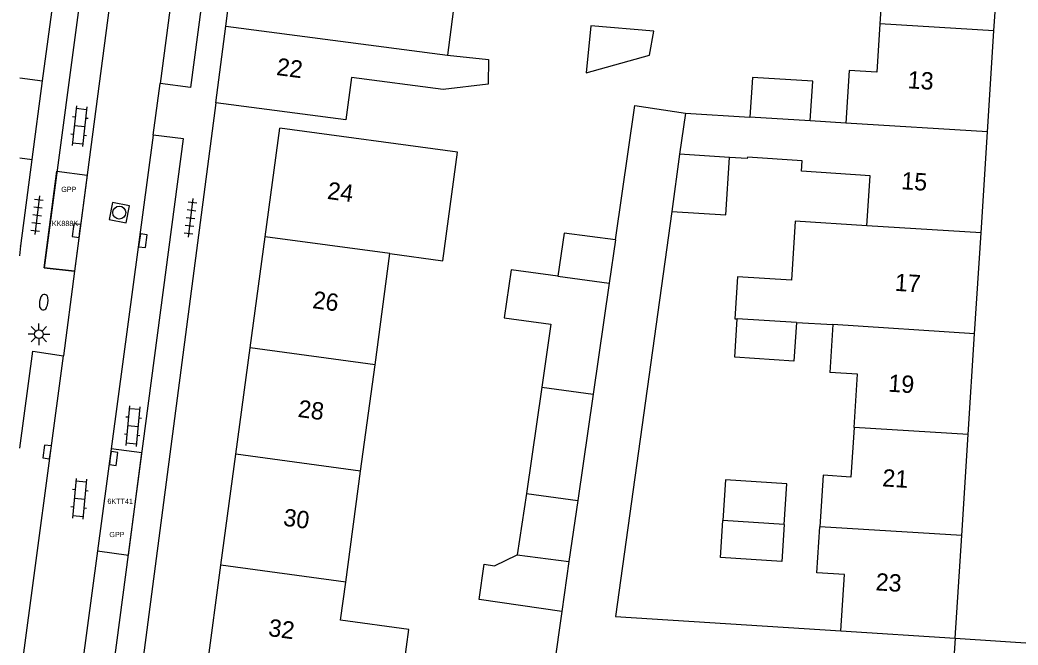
# Model space of a CAD drawing. Extents: x 132994 to 136000, y 393499 to 395512.
# Drawn here: x 133000 to 133057.6, y 395239.4 to 395275.5 of the extents above; entities that cross this region are included whole.
import ezdxf

# ---------------------------------------------------------------- set-up
doc = ezdxf.new("R2010")
doc.units = 0
for name, color, linetype in [('bp-anno-kenteken', 7, 'Continuous'), ('bp-grn-parkeervak', 7, 'Continuous'), ('gg-afsc-erfafscheiding', 7, 'Continuous'), ('gg-afsc-hekwerk', 7, 'Continuous'), ('gg-anno-huisnummerreeks BGT', 7, 'Continuous'), ('gg-bbg-gedigitaliseerde bebouwing', 7, 'Continuous'), ('gg-bbg-gedigitaliseerde bijgebouw', 7, 'Continuous'), ('gg-bbg-hoofdgebouw', 7, 'Continuous'), ('gg-bbg-luifel en loopbrug', 7, 'Continuous'), ('gg-bbg-tussenscheiding', 7, 'Continuous'), ('gg-knt-verharding', 7, 'Continuous'), ('gg-knt-verharding nz', 7, 'Continuous'), ('gt-symb-brandkraan', 7, 'Continuous'), ('gt-symb-klinker verharding', 7, 'Continuous'), ('gt-symb-kolk', 7, 'Continuous'), ('gt-symb-lichtmast', 7, 'Continuous'), ('gt-symb-rioolschacht', 7, 'Continuous'), ('gt-symb-tegel verharding', 7, 'Continuous'), ('kenmerkpunt gehandicapten parkeerplaats', 7, 'Continuous')]:
    doc.layers.add(name, color=color, linetype=linetype)

# ---------------------------------------------------------------- blocks, each defined once
blk = doc.blocks.new('gt0-KOLK')
at = {"layer": 'gt-symb-kolk'}
blk.add_lwpolyline([(0, 0), (0.375, 0), (0.375, 0.4), (-0.375, 0.4), (-0.375, 0), (0, 0)], dxfattribs=at)
blk = doc.blocks.new('gt0-TEG1')
at = {"layer": 'gt-symb-tegel verharding'}
for p, q in [((-1.125, 0), (1.125, 0)), ((-0.9, -0.25), (-0.9, 0.25)), ((-0.45, -0.25), (-0.45, 0.25)), ((0, -0.25), (0, 0.25)), ((0.45, -0.25), (0.45, 0.25)), ((0.9, -0.25), (0.9, 0.25))]:
    blk.add_line(p, q, dxfattribs=at)
blk = doc.blocks.new('gt0-RS')
at = {"layer": 'gt-symb-rioolschacht'}
blk.add_lwpolyline([(-0.5, -0.5), (0.5, -0.5), (0.5, 0.5), (-0.5, 0.5)], close=True, dxfattribs=at)
blk.add_circle((0, 0), 0.375, dxfattribs=at)
blk = doc.blocks.new('gt0-KL1')
at = {"layer": 'gt-symb-klinker verharding'}
for p, q in [((-1.15, 0.3), (1.15, 0.3)), ((-1, -0.3), (-1, 0.3)), ((-0.5, 0.3), (-0.5, 0.45)), ((0, -0.3), (0, 0.3)), ((0.5, 0.3), (0.5, 0.45)), ((1, -0.3), (1, 0.3)), ((-1.15, -0.3), (1.15, -0.3)), ((-0.5, -0.45), (-0.5, -0.3)), ((0.5, -0.45), (0.5, -0.3))]:
    blk.add_line(p, q, dxfattribs=at)
blk = doc.blocks.new('gt0-LMAST')
at = {"layer": 'gt-symb-lichtmast'}
for p, q in [((-0.005, 0.246), (-0.005, 0.621)), ((-0.182, 0.173), (-0.447, 0.438)), ((0.172, 0.173), (0.437, 0.438)), ((-0.255, -0.004), (-0.63, -0.004)), ((-0.182, -0.181), (-0.447, -0.446)), ((-0.005, -0.254), (-0.005, -0.629)), ((0.437, -0.446), (0.172, -0.181)), ((0.245, -0.004), (0.62, -0.004))]:
    blk.add_line(p, q, dxfattribs=at)
blk.add_circle((-0.005, -0.004), 0.25, dxfattribs=at)
blk = doc.blocks.new('gt0-BR')
at = {"layer": 'gt-symb-brandkraan'}
for centre, radius, start, end in [((-0.244, 0), 0.206, 107.56694, 252.43307), ((0.599, -2.664), 3, 106.89205, 107.56694), ((0, -0.691), 0.938, 73.10799, 106.89205), ((-0.599, -2.664), 3, 72.43309, 73.10799), ((0.244, 0), 0.206, 287.56695, 72.43309), ((0.599, 2.664), 3, 252.43307, 253.10797), ((0, 0.691), 0.938, 253.10797, 286.89206), ((-0.599, 2.664), 3, 286.89206, 287.56695)]:
    blk.add_arc(centre, radius, start, end, dxfattribs=at)

msp = doc.modelspace()

# ---------------------------------------------------------------- linework, layer by layer
at = {"layer": 'bp-grn-parkeervak'}
for points in [[(133003.147, 395261.009), (133001.393, 395261.218), (133002.134, 395266.793), (133003.879, 395266.563), (133003.147, 395261.009)], [(133004.476, 395244.873), (133006.259, 395244.635), (133007.04, 395250.53), (133005.262, 395250.767), (133004.476, 395244.873)]]:
    msp.add_lwpolyline(points, dxfattribs=at)
at = {"layer": 'gg-afsc-erfafscheiding'}
for p, q in [((133031.274, 395241.382), (133030.751, 395237.839)), ((133053.96, 395239.83), (133058.979, 395239.513))]:
    msp.add_line(p, q, dxfattribs=at)
for points in [[(133034.364, 395262.817), (133035.481, 395270.573), (133038.409, 395270.137)], [(133037.608, 395264.469), (133034.37, 395241.085), (133047.367, 395240.253)]]:
    msp.add_lwpolyline(points, dxfattribs=at)
at = {"layer": 'gg-afsc-hekwerk'}
msp.add_line((133053.96, 395239.83), (133053.832, 395237.8), dxfattribs=at)
at = {"layer": 'gg-bbg-gedigitaliseerde bebouwing'}
for p, q in [((133038.409, 395270.137), (133038.064, 395267.759)), ((133038.409, 395270.137), (133042.121, 395269.899)), ((133047.653, 395269.564), (133045.603, 395269.695)), ((133040.937, 395267.576), (133038.064, 395267.759)), ((133000, 395262.491), (133000.045, 395262.485)), ((133020.486, 395255.619), (133021.35, 395262.031)), ((133044.797, 395258.05), (133046.908, 395257.931)), ((133046.908, 395257.931), (133046.731, 395255.173)), ((133019.658, 395249.475), (133020.486, 395255.619)), ((133018.795, 395243.07), (133019.658, 395249.475)), ((133047.367, 395240.253), (133053.96, 395239.83))]:
    msp.add_line(p, q, dxfattribs=at)
for points in [[(133056.57, 395280.69), (133048.398, 395281.214), (133048.214, 395278.337), (133049.808, 395278.235), (133049.619, 395275.289)], [(133020.021, 395278.41), (133019.794, 395276.674), (133025.002, 395275.992), (133024.672, 395273.473)], [(133049.619, 395275.289), (133049.439, 395272.492), (133047.847, 395272.594), (133047.653, 395269.564)], [(133024.672, 395273.473), (133027.029, 395273.227), (133027.012, 395271.801), (133024.415, 395271.509), (133019.13, 395272.201), (133018.808, 395269.746), (133011.3, 395270.73)], [(133021.35, 395262.031), (133024.399, 395261.62), (133025.243, 395267.886), (133014.99, 395269.27)], [(133048.87, 395263.641), (133049.055, 395266.525), (133045.091, 395266.779), (133045.13, 395267.391), (133041.974, 395267.594), (133041.968, 395267.51), (133040.937, 395267.576)], [(133048.87, 395263.641), (133044.72, 395263.897), (133044.509, 395260.5), (133041.406, 395260.693), (133041.256, 395258.264), (133041.387, 395258.256)], [(133048.124, 395251.992), (133048.321, 395255.071), (133046.731, 395255.173)], [(133048.124, 395251.992), (133047.941, 395249.132), (133046.351, 395249.234), (133046.161, 395246.267)], [(133047.367, 395240.253), (133047.577, 395243.505), (133045.988, 395243.607), (133046.161, 395246.267)], [(133017.96, 395236.875), (133021.901, 395236.344), (133022.439, 395240.334), (133018.498, 395240.866), (133018.795, 395243.07)]]:
    msp.add_lwpolyline(points, dxfattribs=at)
at = {"layer": 'gg-bbg-gedigitaliseerde bijgebouw'}
for p, q in [((133034.364, 395262.817), (133034.004, 395260.318)), ((133034.004, 395260.318), (133033.082, 395253.921)), ((133030.114, 395254.321), (133029.23, 395248.185)), ((133033.082, 395253.921), (133032.197, 395247.785)), ((133029.23, 395248.185), (133028.695, 395244.654)), ((133032.197, 395247.785), (133031.662, 395244.253)), ((133028.695, 395244.654), (133031.662, 395244.253))]:
    msp.add_line(p, q, dxfattribs=at)
for points in [[(133032.677, 395272.464), (133036.329, 395273.49), (133036.566, 395274.858), (133032.939, 395275.174), (133032.677, 395272.464)], [(133045.603, 395269.695), (133045.749, 395271.974), (133042.267, 395272.198), (133042.121, 395269.899)], [(133034.364, 395262.817), (133031.397, 395263.218), (133031.037, 395260.72)], [(133031.037, 395260.72), (133028.337, 395261.086), (133027.94, 395258.332), (133030.64, 395257.967), (133030.114, 395254.321)], [(133044.797, 395258.05), (133044.654, 395255.826), (133041.245, 395256.044), (133041.387, 395258.256)], [(133044.096, 395246.4), (133044.246, 395248.738), (133040.702, 395248.966), (133040.551, 395246.627)], [(133044.096, 395246.4), (133043.96, 395244.262), (133040.414, 395244.489), (133040.551, 395246.627)]]:
    msp.add_lwpolyline(points, dxfattribs=at)
at = {"layer": 'gg-bbg-hoofdgebouw'}
for p, q in [((133056.199, 395274.88), (133056.57, 395280.69)), ((133011.879, 395275.149), (133012.437, 395279.404)), ((133001.307, 395271.998), (133001.996, 395277.192)), ((133011.3, 395270.73), (133011.879, 395275.149)), ((133055.827, 395269.055), (133056.199, 395274.88)), ((133000.706, 395267.467), (133001.307, 395271.998)), ((133014.145, 395263.002), (133014.99, 395269.27)), ((133055.455, 395263.231), (133055.827, 395269.055)), ((133000.045, 395262.485), (133000.706, 395267.467)), ((133013.281, 395256.59), (133014.145, 395263.002)), ((133055.083, 395257.407), (133055.455, 395263.231)), ((133054.711, 395251.582), (133055.083, 395257.407)), ((133012.453, 395250.446), (133013.281, 395256.59)), ((133054.339, 395245.757), (133054.711, 395251.582)), ((133011.589, 395244.04), (133012.453, 395250.446)), ((133053.96, 395239.83), (133054.339, 395245.757)), ((133010.754, 395237.846), (133011.589, 395244.04))]:
    msp.add_line(p, q, dxfattribs=at)
at = {"layer": 'gg-bbg-luifel en loopbrug'}
for p, q in [((133038.064, 395267.759), (133037.608, 395264.469)), ((133031.662, 395244.253), (133031.274, 395241.382))]:
    msp.add_line(p, q, dxfattribs=at)
for points in [[(133037.608, 395264.469), (133040.732, 395264.275), (133040.937, 395267.576)], [(133031.274, 395241.382), (133026.5, 395242.07), (133026.793, 395244.104), (133027.386, 395244.018), (133028.695, 395244.654)]]:
    msp.add_lwpolyline(points, dxfattribs=at)
at = {"layer": 'gg-bbg-tussenscheiding'}
for p, q in [((133011.879, 395275.149), (133024.672, 395273.473)), ((133056.199, 395274.88), (133049.619, 395275.289)), ((133000, 395272.171), (133001.307, 395271.998)), ((133045.603, 395269.695), (133042.121, 395269.899)), ((133055.827, 395269.055), (133047.653, 395269.564)), ((133000, 395267.561), (133000.706, 395267.467)), ((133055.455, 395263.231), (133048.87, 395263.641)), ((133021.35, 395262.031), (133014.145, 395263.002)), ((133031.037, 395260.72), (133034.004, 395260.318)), ((133044.797, 395258.05), (133041.387, 395258.256)), ((133055.083, 395257.407), (133046.908, 395257.931)), ((133020.486, 395255.619), (133013.281, 395256.59)), ((133030.114, 395254.321), (133033.082, 395253.921)), ((133054.711, 395251.582), (133048.124, 395251.992)), ((133019.658, 395249.475), (133012.453, 395250.446)), ((133029.23, 395248.185), (133032.197, 395247.785)), ((133044.096, 395246.4), (133040.551, 395246.627)), ((133054.339, 395245.757), (133046.161, 395246.267)), ((133018.795, 395243.07), (133011.589, 395244.04))]:
    msp.add_line(p, q, dxfattribs=at)
at = {"layer": 'gg-knt-verharding'}
for p, q in [((133007.677, 395268.872), (133008.084, 395271.856)), ((133000, 395261.9), (133000.045, 395262.485)), ((133003.147, 395261.009), (133002.503, 395256.135))]:
    msp.add_line(p, q, dxfattribs=at)
for points in [[(133010.704, 395291.594), (133012.45, 395291.376), (133009.834, 395271.625), (133008.084, 395271.856)], [(133006.459, 395286.134), (133004.737, 395286.363), (133001.393, 395261.218), (133003.147, 395261.009)], [(133011.3, 395270.73), (133005.42, 395225.78), (133004.685, 395219.071)], [(133001.31, 395220.939), (133003.085, 395220.676), (133009.442, 395268.657), (133007.677, 395268.872)], [(133000, 395250.792), (133000.742, 395256.406), (133002.503, 395256.135)]]:
    msp.add_lwpolyline(points, dxfattribs=at)
at = {"layer": 'gg-knt-verharding nz'}
for p, q in [((133010.704, 395291.594), (133008.084, 395271.856)), ((133006.459, 395286.134), (133003.147, 395261.009)), ((133007.677, 395268.872), (133003.368, 395236.57)), ((133000, 395237.338), (133002.503, 395256.135))]:
    msp.add_line(p, q, dxfattribs=at)

# ---------------------------------------------------------------- block references
at = {"layer": 'gt-symb-brandkraan', "rotation": -98.04906170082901}
msp.add_blockref('gt0-BR', (133001.373, 395259.229), dxfattribs=at)
at = {"layer": 'gt-symb-klinker verharding'}
for p, rotation in [((133003.436, 395269.388), -96.03000880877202), ((133006.519, 395252.075), -95.33444003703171), ((133003.436, 395247.886), -95.33444003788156)]:
    msp.add_blockref('gt0-KL1', p, dxfattribs=dict(at, rotation=rotation))
at = {"layer": 'gt-symb-kolk'}
for p, rotation in [((133003.457, 395263.328), 82.53402593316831), ((133006.896, 395262.799), -97.64386978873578), ((133001.762, 395250.559), 82.41293093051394), ((133005.211, 395250.234), -97.53025334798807)]:
    msp.add_blockref('gt0-KOLK', p, dxfattribs=dict(at, rotation=rotation))
at = {"layer": 'gt-symb-lichtmast'}
msp.add_blockref('gt0-LMAST', (133001.103, 395257.379), dxfattribs=at)
at = {"layer": 'gt-symb-rioolschacht', "rotation": -100.95043426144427}
msp.add_blockref('gt0-RS', (133005.73, 395264.395), dxfattribs=at)
at = {"layer": 'gt-symb-tegel verharding', "rotation": -97.00425924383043}
for p in [(133000.986, 395264.249), (133009.839, 395264.091)]:
    msp.add_blockref('gt0-TEG1', p, dxfattribs=at)

# ---------------------------------------------------------------- texts
at = {"layer": 'bp-anno-kenteken'}
for s, p in [('KK888K', (133001.838, 395263.621)), ('6KTT41', (133005.046, 395247.587))]:
    msp.add_text(s, height=0.3, dxfattribs=at).set_placement(p)
at = {"layer": 'gg-anno-huisnummerreeks BGT'}
for s, rotation, p in [('22', 352.5, (133014.762, 395272.341)), ('13', 356.3, (133051.201, 395271.574)), ('24', 352.3, (133017.692, 395265.193)), ('15', 356.3, (133050.829, 395265.75)), ('17', 356.3, (133050.455, 395259.885)), ('26', 352.3, (133016.843, 395258.889)), ('19', 356.3, (133050.083, 395254.065)), ('28', 352.3, (133015.997, 395252.611)), ('21', 356.3, (133049.734, 395248.601)), ('30', 352.3, (133015.151, 395246.335)), ('23', 356.3, (133049.351, 395242.6)), ('32', 352.3, (133014.292, 395239.968))]:
    msp.add_text(s, height=1, rotation=rotation, dxfattribs=at).set_placement(p)
at = {"layer": 'kenmerkpunt gehandicapten parkeerplaats'}
for p in [(133002.38, 395265.586), (133005.158, 395245.668)]:
    msp.add_text('GPP', height=0.3, dxfattribs=at).set_placement(p)

doc.saveas('drawing.dxf')
